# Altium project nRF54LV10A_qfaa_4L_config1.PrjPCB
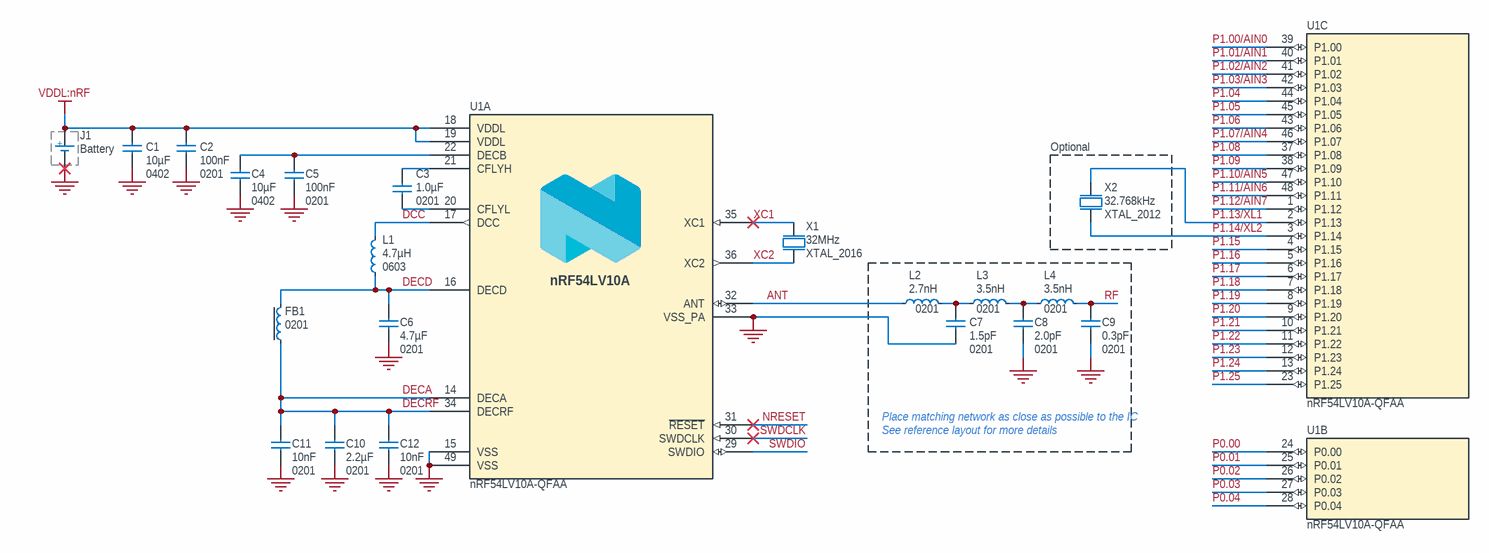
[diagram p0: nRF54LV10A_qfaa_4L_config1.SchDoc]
Revision: 0.3
1 sheet, 21 parts. Net scope: global (net labels, ports and power ports of the same name join across sheets).
Board file: nRF54LV10A_qfaa_4L_config1.PcbDoc

## Sheet nRF54LV10A_qfaa_4L_config1.SchDoc
size A4; PCAName: Reference Layout; Organization: Nordic Semiconductor; Revision: 0.3; SheetNumber: 1; SheetTotal: 1; DrawnBy: DABA; DocumentSize: A4; RefLayoutTitle: VDDL:nRF supplied by 1.5 V battery, Enabled DC/DC; Device: nRF54LV10A-QFAA; Classification: Public; Config: 1

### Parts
C1  10µF  Footprint Doc: 0402  [CAPC1005X04L]
C2  100nF  Footprint Doc: 0201  [CAPC0603X03L_C]
C3  1.0µF  Footprint Doc: 0201  [CAPC0603X03L_C]
C4  10µF  Footprint Doc: 0402  [CAPC1005X04L]
C5  100nF  Footprint Doc: 0201  [CAPC0603X03L_C]
C6  4.7µF  Footprint Doc: 0201  [CAPC0603X03L_C]
C7  1.5pF  Footprint Doc: 0201  [CAPC0603X03L_C]
C8  2.0pF  Footprint Doc: 0201  [CAPC0603X03L_C]
C9  0.3pF  Footprint Doc: 0201  [CAPC0603X03L_C]
C10  2.2µF  Footprint Doc: 0201  [CAPC0603X03L_C]
C11  10nF  Footprint Doc: 0201  [CAPC0603X03L_C]
C12  Footprint Doc: 0201  [CAPC0603X03L_C]  (hidden comment: 10nF)
FB1  Footprint Doc: 0201  [INDC0603X03L_C]  (hidden comment: 120R/0.2A)
J1  Battery  [TP_2x1mm_TH]  (graphical)
L1  4.7µH  Footprint Doc: 0603  [INDC1608X06L]
L2  2.7nH  Footprint Doc: 0201  [INDC0603X03L_C]
L3  3.5nH  Footprint Doc: 0201  [INDC0603X03L_C]
L4  3.5nH  Footprint Doc: 0201  [INDC0603X03L_C]
U1  nRF54LV10A-QFAA  [QFN40P600X600X90-48N]  (parts A,B,C of 3)
X1  32MHz  Footprint Doc: XTAL_2016  [BT-XTAL_2016]
X2  32.768kHz  [XTAL_2012]

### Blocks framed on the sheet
Optional: X2

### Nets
GND: C1.1 C2.1 C4.1 C5.2 C6.1 C7.1 C8.1 C9.1 C10.2 C11.1 C12.1 J1.1(GND) U1.15(VSS) U1.33(VSS_PA) U1.49(VSS) X1.2(GND) X1.4(GND)
VDDL:nRF: C1.2 C2.2 J1.2(V+) U1.18(VDDL) U1.19(VDDL)
ANT: L2.1 U1.32(ANT)
DCC: L1.1 U1.17(DCC)
DECA: C10.1 C11.2 C12.2 FB1.2 U1.14(DECA) U1.34(DECRF)  [also labelled DECRF]
DECD: C6.2 FB1.1 L1.2 U1.16(DECD)
NRESET: U1.31(~{RESET})
P0.00: U1.24(P0.00)
P0.01: U1.25(P0.01)
P0.02: U1.26(P0.02)
P0.03: U1.27(P0.03)
P0.04: U1.28(P0.04)
P1.00/AIN0: U1.39(P1.00)
P1.01/AIN1: U1.40(P1.01)
P1.02/AIN2: U1.41(P1.02)
P1.03/AIN3: U1.42(P1.03)
P1.04: U1.44(P1.04)
P1.05: U1.45(P1.05)
P1.06: U1.43(P1.06)
P1.07/AIN4: U1.46(P1.07)
P1.08: U1.37(P1.08)
P1.09: U1.38(P1.09)
P1.10/AIN5: U1.47(P1.10)
P1.11/AIN6: U1.48(P1.11)
P1.12/AIN7: U1.1(P1.12)
P1.13/XL1: U1.2(P1.13) X2.2(out)
P1.14/XL2: U1.3(P1.14) X2.1(inp)
P1.15: U1.4(P1.15)
P1.16: U1.5(P1.16)
P1.17: U1.6(P1.17)
P1.18: U1.7(P1.18)
P1.19: U1.8(P1.19)
P1.20: U1.9(P1.20)
P1.21: U1.10(P1.21)
P1.22: U1.11(P1.22)
P1.23: U1.12(P1.23)
P1.24: U1.13(P1.24)
P1.25: U1.23(P1.25)
RF: C9.2 L4.2
SWDCLK: U1.30(SWDCLK)
SWDIO: U1.29(SWDIO)
XC1: U1.35(XC1) X1.1(inp)
XC2: U1.36(XC2) X1.3(out)
NetC3_1: C3.1 U1.20(CFLYL)
NetC3_2: C3.2 U1.21(CFLYH)
NetC4_2: C4.2 C5.1 U1.22(DECB)
NetC7_2: C7.2 L2.2 L3.1
NetC8_2: C8.2 L3.2 L4.1

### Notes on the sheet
- See reference layout for more details
- Place matching network as close as possible to the IC

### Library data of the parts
C1 C4 = C0402-10µF-6.3V-X6S: Capacitor, X6S, ±20%, 6.3V; Manufacturer: N.A.; Part number NEMS: 100200478; Component Status: Active; Pad Count: 2
C2 = C0201-100n-10V-X7R: Capacitor, X7R, ±10%, 100nF, 10V; Manufacturer: N.A.; Part number NEMS: 100200469; Component Status: Active; Pad Count: 2
C3 = C0201-1µ0-6.3V: Capacitor, Ceramic, X5R, ±20%, 6.3V; Manufacturer: Murata; Manufacturer Part Number: GRM033R60J105MEA2D; Part number NEMS: 100200387; Component Status: Active; Pad Count: 2; Artikkelnr Noca: N.A.
C5 = C0201-100n-10V-X7R: Capacitor, X7R, ±10%; Manufacturer: N.A.; Part number NEMS: 100200469; Note: 10V; Pad Count: 2; Component Status: Active
C6 = C0201-4.7µ-6V3-X5R-GRM035R60J475ME15J: Capacitor, Ceramic, X5R, ±20%, 6.3V; Manufacturer: Murata; Part number NEMS: 100200685; Component Status: Active; Pad Count: 2; Note: -55°C ~ 85°C; Artikkelnr Noca: N.A.
C7 = C0201-1.5p-25V-NP0-GJM0335C1E1R5WB01: Capacitor, NP0, ±0.05pF, 25V, High Q; Manufacturer: Murata; Part number NEMS: 100200477; Component Status: Active; Pad Count: 2; Artikkelnr Noca: N.A.
C8 = C0201-2.0p-HQ-Murata: Capacitor, NP0, ±0.05pF, 25V; Manufacturer: Murata; Manufacturer Part Number: GJM0335C1E2R0WB01; Part number IPS: 00000001775; Part number NEMS: 100200419; Component Status: Active; Pad Count: 2; Artikkelnr Noca: N.A.
C9 = C0201-0.3p-50V-GRM0335C1HR30BA01: Capacitor, C0G, ±0.1pF, 50V; Manufacturer: Murata; Part number NEMS: 100200650; Component Status: Active; Pad Count: 2; Artikkelnr Noca: N.A.
C10 = C0201-2µ2-2.5V-X6T-GRM033D80E225ME47D: Capacitor, Ceramic, 2.2µF 2.5V X6T 0201,±20%; Manufacturer: Murata; Part number NEMS: 100200527; Component Status: Active; Pad Count: 2; Note: 2.5V, 20%, X6T; Artikkelnr Noca: N.A.
C11 C12 = C0201-10n-6.3V-X7R: Capacitor, X7R, 6.3V; Manufacturer: Murata; Manufacturer Part Number: GRM033R70J103KA01D; Part number NEMS: 100200407; Component Status: Active; Pad Count: 2; Artikkelnr Noca: N.A.
FB1 = FB0201-120R@100M-200mA-BLM03AG121SN1D: Ferrite Bead, 120 Ohm @ 100MHz, 200mA, 500 mOhm Max; Manufacturer: Murata; Part number NEMS: 100300419; Component Status: Active; Pad Count: 2; Artikkelnr Noca: N.A.
J1 = Battery_TP: Manufacturer: N.A.; Part number NEMS: 101800006; Component Status: Active; Pad Count: 3
L1 = L0603-4µ7-MLZ1608M4R7WT000: Inductor, 120mA, ±20%, 0.65R; Manufacturer: TDK Corporation; Part number NEMS: 100300440; Component Status: Active; Pad Count: 2; Note: Power Inductor ±20%; Artikkelnr Noca: N.A.
L2 = L0201-2n7-HQ-Murata: Inductor, 600mA, ±0.1ｎH, 120mOhm; Manufacturer: Murata; Manufacturer Part Number: LQP03HQ2N7B02; Part number IPS: 00000001753; Part number NEMS: 100300214; Component Status: Active; Pad Count: 2; Note: -55°C ~ 125°C; Artikkelnr Noca: N.A.
L3 L4 = L0201-3n5-HQ-Murata: Inductor, 500mA, ±0.1ｎH, 170mOhm; Manufacturer: Murata; Manufacturer Part Number: LQP03HQ3N5B02; Part number NEMS: 100300222; Component Status: Active; Pad Count: 2; Note: -55°C ~ 125°C; Artikkelnr Noca: N.A.
U1 = nRF54LV10A-QFAA: Multi-protocol Bluetooth Low Energy, IEEE 802.15.4 and 2.4GHz proprietary Wireless MCU; Manufacturer: Nordic Semiconductor; Part number NEMS: 102000335; Component Status: Active; Pad Count: 49; Note: N.A.
X1 = XTAL_SMD2016_32MHz_8pF_Kyocera: XTAL SMD 2016, 32MHz, Cl=8pF, Tot: ±40ppm; Manufacturer Part Number: CX2016DB32000D0WZRC1; Part number IPS: 00000007827; Part number Norautron: 26511136; Part number NEMS: 101600039; Component Status: Active; Pad Count: 4; Note: XTAL SMD 32.000MHz; Artikkelnr Noca: 22010022
X2 = XTAL_SMD2012_32.768kHz_9pF_TXC: XTAL SMD 2012, 32.768kHz, 9pF, ±20ppm; Manufacturer: TXC Corporation; Manufacturer Part Number: 9HT11-32.768KDZC-T; Part number NEMS: 101600107; Component Status: Active; Pad Count: 2; Note: XTAL SMD 32.768kHz; Artikkelnr Noca: N.A.

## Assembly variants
default: not fitted C13 C14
